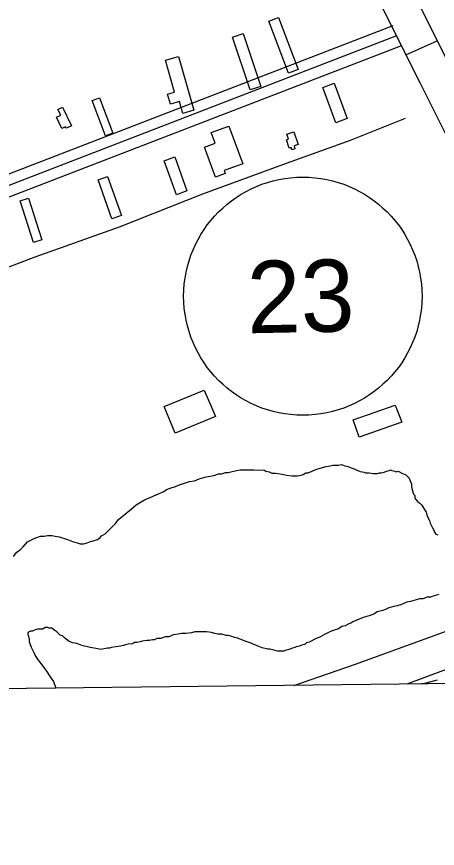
# Model space of a CAD drawing. Extents: x 3684037 to 3722149, y 433263 to 459021.
# Drawn here: x 3707277 to 3707859, y 438677 to 439830 of the extents above; entities that cross this region are included whole.
import ezdxf

# ---------------------------------------------------------------- set-up
doc = ezdxf.new("R2010")
doc.units = 0
for name, color, linetype in [('V-BLDG-OTLN', 7, 'Continuous'), ('V-GRID-FRAM', 7, 'Continuous'), ('V-LEVE-TOET', 7, 'Continuous'), ('V-RIVR-EDGE', 7, 'Continuous'), ('V-ROAD-CNTR', 7, 'Continuous'), ('V-ROAD-IDEN', 7, 'Continuous'), ('V-SITE-VEGE', 7, 'Continuous'), ('V-TOPO-SHOR', 7, 'Continuous')]:
    doc.layers.add(name, color=color, linetype=linetype)

msp = doc.modelspace()

# ---------------------------------------------------------------- linework, layer by layer
at = {"layer": 'V-BLDG-OTLN'}
for points in [[(3707638.9, 439828.7), (3707666.2, 439756.5), (3707653, 439751.5), (3707625.6, 439823.6)], [(3707590.3, 439806.6), (3707614.8, 439733.2), (3707600.1, 439728.3), (3707575.6, 439801.6)], [(3707500.6, 439774.8), (3707522, 439700.2), (3707506.8, 439695.8), (3707502.1, 439712.2), (3707489.5, 439708.6), (3707485.5, 439722.5), (3707495.3, 439725.3), (3707482.6, 439769.6)], [(3707718.7, 439682.9), (3707700.6, 439731.9), (3707716, 439737.6), (3707734.1, 439688.6)], [(3707399.6, 439664.7), (3707381.1, 439713.7), (3707391.3, 439717.6), (3707409.8, 439668.5)], [(3707340, 439704.4), (3707352.5, 439678.5), (3707345.5, 439675.2), (3707344.4, 439677.4), (3707339.2, 439674.9), (3707331.7, 439690.6), (3707337.6, 439693.4), (3707333.7, 439701.4)], [(3707589.7, 439626.2), (3707563.8, 439616.6), (3707565.2, 439612.7), (3707551.9, 439607.7), (3707536.5, 439649), (3707551.2, 439654.5), (3707545.8, 439669.2), (3707570.2, 439678.3)], [(3707650.6, 439667.1), (3707660.5, 439670.3), (3707666.2, 439652.8), (3707660.6, 439650.9), (3707661.9, 439646.8), (3707657.7, 439645.5), (3707656.7, 439648.8), (3707654, 439647.9), (3707650.3, 439659.3), (3707652.8, 439660.1)], [(3707495.5, 439635.5), (3707512.4, 439588.5), (3707497.7, 439583.2), (3707480.8, 439630.2)], [(3707408.4, 439549.8), (3707389.4, 439604), (3707402.6, 439608.6), (3707421.6, 439554.4)], [(3707293, 439578.2), (3707311.5, 439520.8), (3707300, 439517.1), (3707281.5, 439574.5)], [(3707551.9, 439275.7), (3707496, 439252.8), (3707480.9, 439289.8), (3707536.3, 439312.5)], [(3707809.9, 439267.8), (3707750.6, 439247.4), (3707742.4, 439271.3), (3707800.7, 439291.4)]]:
    msp.add_lwpolyline(points, close=True, dxfattribs=at)
at = {"layer": 'V-GRID-FRAM'}
msp.add_lwpolyline([(3688058.9, 456858.9), (3719789.3, 457228.1), (3720008.8, 439046.9), (3688262.6, 438677.5), (3688058.9, 456858.9)], dxfattribs=at)
at = {"layer": 'V-LEVE-TOET'}
for points in [[(3707660.4, 438903.2), (3707744.1, 438932.2), (3707908, 438991.9), (3707952.7, 439006.9), (3707995.6, 439019.6), (3708048.1, 439034.1), (3708079.1, 439043.2), (3708092.2, 439043.8), (3708101.2, 439040.8), (3708104.7, 439039.7), (3708107.8, 439030.7), (3708106.6, 439019.4), (3708109.7, 438988.4), (3708127.7, 438941.9), (3708140.5, 438908.8)], [(3708085.8, 438908.1), (3708078.3, 438928.6), (3708059.6, 438971.5), (3708055.4, 438980.4), (3708047.6, 438982.8), (3708006.5, 438971.9), (3707867.6, 438923.7), (3707816.9, 438905)]]:
    msp.add_lwpolyline(points, dxfattribs=at)
at = {"layer": 'V-RIVR-EDGE'}
msp.add_spline([(3705459.3, 448025.4), (3705478.2, 447991), (3705490.6, 447962.7), (3705497.9, 447946.9), (3705515.2, 447915.3), (3705550.2, 447853.8), (3705577.2, 447806.4), (3705592.1, 447777.2), (3705613, 447735.5), (3705627.1, 447702.7), (3705648.4, 447660.6), (3705670.9, 447613.3), (3705688.6, 447575.6), (3705703.1, 447542.8), (3705728.1, 447487.8), (3705750.2, 447433.1), (3705764.2, 447399.5), (3705787.6, 447350.5), (3705800.4, 447321.8), (3705823.8, 447277.7), (3705853.1, 447212.9), (3705867.2, 447179.7), (3705884.5, 447148.5), (3705906.2, 447095.5), (3705936, 447039.6), (3705952.5, 446996.3), (3705954.5, 446986.6), (3705964.5, 446959.1), (3705978.2, 446928.3), (3706001.9, 446883.8), (3706017.2, 446850.2), (3706031.3, 446824.3), (3706060.3, 446774.8), (3706084.9, 446736.8), (3706095.8, 446723.4), (3706096.2, 446720.2), (3706091.3, 446714.5), (3706089.7, 446713.3), (3706090.5, 446708.9), (3706096.1, 446705.6), (3706103, 446703.6), (3706108.6, 446696.7), (3706116.3, 446683.3), (3706130, 446657), (3706163.4, 446591.8), (3706169.4, 446575.6), (3706187.1, 446537.6), (3706212.8, 446473.6), (3706230.1, 446432.3), (3706247.4, 446398.3), (3706265.1, 446371.2), (3706278.8, 446345.3), (3706293.7, 446309.7), (3706314.6, 446262.3), (3706333.5, 446225.8), (3706356, 446180.1), (3706380.2, 446133.5), (3706396.3, 446102.4), (3706412.8, 446074.8), (3706429.7, 446038.8), (3706447, 445997.9), (3706455.4, 445962.3), (3706478.2, 445886.2), (3706492.7, 445852.2), (3706510.4, 445809.7), (3706528.1, 445771.7), (3706558.3, 445705.3), (3706582.8, 445657.1), (3706597.7, 445624.3), (3706628.3, 445558.3), (3706659.6, 445483), (3706677.7, 445432.8), (3706697, 445381), (3706750.1, 445262.4), (3706782.6, 445193.2), (3706806.8, 445141.8), (3706827.7, 445093.6), (3706851, 445029.3), (3706864.2, 444984.3), (3706871.8, 444949.5), (3706889.5, 444896.9), (3706899.9, 444865.8), (3706912.4, 444832.2), (3706928.8, 444798.2), (3706942.5, 444773.5), (3706966.3, 444725.3), (3706990.4, 444679.5), (3707017, 444624.5), (3707033.9, 444586), (3707080.5, 444482), (3707095.4, 444444.7), (3707112.3, 444405.1), (3707123.1, 444381.2), (3707171.4, 444273.5), (3707203.2, 444200.6), (3707218, 444163.8), (3707250.2, 444096.2), (3707257.4, 444074.3), (3707269.9, 444041.6), (3707288.4, 443990.6), (3707304, 443950.1), (3707343, 443838), (3707365.9, 443772), (3707378.7, 443728.7), (3707379.9, 443714.1), (3707381.1, 443702.8), (3707387.5, 443682.2), (3707398.3, 443657.1), (3707418.1, 443619), (3707439, 443578.5), (3707454.3, 443542.1), (3707473.1, 443492.7), (3707483.2, 443464.4), (3707531.1, 443368), (3707542.7, 443345), (3707550.8, 443323.9), (3707556.8, 443302.5), (3707556.8, 443297.6), (3707558.8, 443289.1), (3707568.4, 443273.3), (3707583.7, 443244.6), (3707593.8, 443221.9), (3707598.2, 443213.4), (3707609.5, 443204.9), (3707611.9, 443195.2), (3707611.9, 443180.6), (3707615.5, 443168.1), (3707621.9, 443150.3), (3707634.4, 443126.8), (3707648.1, 443102.1), (3707655.3, 443081.8), (3707660.5, 443073.3), (3707674.2, 443051.5), (3707678.6, 443034.1), (3707682.6, 443015.5), (3707689.5, 442998.5), (3707701.9, 442964.5), (3707714, 442928.4), (3707721.2, 442903.3), (3707726.4, 442888.8), (3707738.1, 442871.8), (3707743.7, 442857.2), (3707744.5, 442845.1), (3707747.3, 442826.1), (3707753.7, 442815.5), (3707763, 442801.3), (3707770.2, 442783.9), (3707772.6, 442762.1), (3707776.2, 442738.2), (3707779.8, 442720), (3707786.6, 442702.6), (3707805.5, 442663.3), (3707822.8, 442627.3), (3707832, 442599.4), (3707839.2, 442573.9), (3707845.7, 442561.3), (3707852.5, 442552.4), (3707860.2, 442541.9), (3707869.5, 442530.6), (3707886.4, 442507.9), (3707898.9, 442479.9), (3707916.1, 442434.6), (3707928.6, 442395.8), (3707943.4, 442356.5), (3707965.6, 442316.4), (3707989.7, 442269), (3708009.8, 442227.7), (3708024.7, 442192.5), (3708061.3, 442114.4), (3708074.2, 442088.5), (3708094.3, 442045.6), (3708116, 441996.6), (3708126.1, 441968.3), (3708137.7, 441927.8), (3708147.3, 441899.5), (3708157.8, 441868.3), (3708179.1, 441812.4), (3708204, 441746.9), (3708227.7, 441693.8), (3708249.8, 441646.1), (3708265.1, 441615.3), (3708271.5, 441595.9), (3708278.4, 441582.1), (3708308.1, 441508.4), (3708330.6, 441457.8), (3708349.9, 441405.2), (3708369.6, 441340.1), (3708384, 441295.6), (3708395.3, 441268.4), (3708411.8, 441234.8), (3708423.4, 441209.3), (3708441.1, 441169.7), (3708458.4, 441135.2), (3708469.3, 441110.5), (3708475.3, 441089.1), (3708486.9, 441061.6), (3708507.1, 441017.4), (3708523.5, 440978.6), (3708539.2, 440935.7), (3708564.1, 440883.1), (3708587.1, 440841.3), (3708595.1, 440826.8), (3708600.4, 440809.4), (3708606.7, 440778.2), (3708615.6, 440755.1), (3708636.9, 440692), (3708652.9, 440644.3), (3708673.4, 440592), (3708688.7, 440554.4), (3708706, 440506.6), (3708725.7, 440462.9), (3708743.4, 440422.4), (3708759.4, 440387.6), (3708800.1, 440293.3), (3708821, 440246.3), (3708835, 440211.5), (3708849.1, 440180.4), (3708876.1, 440124.9), (3708892.2, 440093.7), (3708912.3, 440054.9), (3708922.3, 440031), (3708932, 439999.8), (3708939.2, 439978.8), (3708948, 439954.1), (3708952.4, 439931.8), (3708956, 439911.6), (3708960, 439899.5), (3708969.6, 439870.3), (3708986.9, 439829.8), (3708999.4, 439794.2), (3709014.7, 439755.4), (3709034.7, 439705.2), (3709046.8, 439671.6), (3709063.3, 439633.1), (3709075.8, 439614.5), (3709093.1, 439592.6), (3709106, 439574.4), (3709121.7, 439548.9), (3709151.5, 439484.1), (3709171.6, 439447.3), (3709197.4, 439407.6), (3709211.1, 439376.8), (3709222.3, 439350.1), (3709240.4, 439308.8), (3709252.9, 439281.7), (3709266.1, 439254.9), (3709271, 439245.6), (3709296.3, 439199.9), (3709313.2, 439159), (3709331.3, 439114.9), (3709341.3, 439082.5), (3709360.3, 439046.5), (3709378.8, 439008.8), (3709407.7, 438944.4), (3709416.4, 438923.6)], degree=3, dxfattribs=at)
at = {"layer": 'V-ROAD-CNTR'}
for points in [[(3706492.4, 442521.2), (3706946.8, 441617.1), (3707489, 440536.5), (3707877, 439759.9), (3708257.7, 438990.5)], [(3706450.1, 442499.9), (3706904.6, 441595.9), (3707446.7, 440515.3), (3707834.7, 439738.8), (3708246.6, 438913.6)], [(3707797.2, 439817.1), (3706879, 439462.6)], [(3707802.6, 439803.1), (3706884.4, 439448.7)], [(3707808, 439789.1), (3706889.8, 439434.7)], [(3707815.5, 439777.1), (3707858.8, 439796.3)]]:
    msp.add_lwpolyline(points, dxfattribs=at)
at = {"layer": 'V-ROAD-IDEN'}
msp.add_circle((3707672.8, 439442.6), 165, dxfattribs=at)
at = {"layer": 'V-SITE-VEGE'}
for p, q in [((3707569.6, 439198.2), (3707581.1, 439201.2)), ((3707581.1, 439201.2), (3707585.9, 439202.1)), ((3707585.9, 439202.1), (3707605.1, 439202.2)), ((3707605.1, 439202.2), (3707610.9, 439201.3)), ((3707610.9, 439201.3), (3707618.6, 439202.2)), ((3707618.6, 439202.2), (3707621.4, 439200.3)), ((3707621.4, 439200.3), (3707626.2, 439199.4)), ((3707681.9, 439198.6), (3707684.8, 439199.6)), ((3707684.8, 439199.6), (3707688.6, 439201.5)), ((3707688.6, 439201.5), (3707693.4, 439203.4)), ((3707693.4, 439203.4), (3707704.9, 439206.4)), ((3707704.9, 439206.4), (3707710.7, 439207.3)), ((3707710.7, 439207.3), (3707714.5, 439208.3)), ((3707714.5, 439208.3), (3707722.2, 439208.3)), ((3707722.2, 439208.3), (3707726.1, 439209.3)), ((3707726.1, 439209.3), (3707730.9, 439207.4)), ((3707730.9, 439207.4), (3707735.7, 439206.5)), ((3707735.7, 439206.5), (3707739.5, 439204.6)), ((3707739.5, 439204.6), (3707742.4, 439203.6)), ((3707742.4, 439203.6), (3707752, 439199.8)), ((3707752, 439199.8), (3707757.8, 439198.9)), ((3707785.6, 439198.9), (3707788.5, 439199.9)), ((3707788.5, 439199.9), (3707792.3, 439200.9)), ((3707792.3, 439200.9), (3707794.3, 439201.9)), ((3707794.3, 439201.9), (3707796.2, 439200.9)), ((3707796.2, 439200.9), (3707800, 439200)), ((3707800, 439200), (3707801.9, 439199)), ((3707801.9, 439199), (3707804.8, 439200)), ((3707804.8, 439200), (3707810.6, 439197.1)), ((3707522.6, 439186.6), (3707529.3, 439189.5)), ((3707529.3, 439189.5), (3707538.9, 439192.4)), ((3707538.9, 439192.4), (3707544.7, 439193.4)), ((3707544.7, 439193.4), (3707549.5, 439194.3)), ((3707549.5, 439194.3), (3707556.2, 439196.3)), ((3707556.2, 439196.3), (3707560, 439196.3)), ((3707560, 439196.3), (3707565.8, 439198.2)), ((3707565.8, 439198.2), (3707569.6, 439198.2)), ((3707626.2, 439199.4), (3707630.1, 439197.5)), ((3707630.1, 439197.5), (3707634.9, 439197.5)), ((3707634.9, 439197.5), (3707641.6, 439196.6)), ((3707641.6, 439196.6), (3707646.4, 439195.6)), ((3707646.4, 439195.6), (3707650.3, 439194.7)), ((3707650.3, 439194.7), (3707657.9, 439193.7)), ((3707657.9, 439193.7), (3707665.6, 439193.8)), ((3707665.6, 439193.8), (3707670.4, 439194.7)), ((3707670.4, 439194.7), (3707673.3, 439195.7)), ((3707673.3, 439195.7), (3707677.1, 439197.6)), ((3707677.1, 439197.6), (3707680, 439197.6)), ((3707680, 439197.6), (3707681.9, 439198.6)), ((3707757.8, 439198.9), (3707759.7, 439197.9)), ((3707759.7, 439197.9), (3707764.5, 439197.9)), ((3707764.5, 439197.9), (3707770.3, 439197)), ((3707770.3, 439197), (3707776, 439197)), ((3707776, 439197), (3707778.9, 439198)), ((3707778.9, 439198), (3707781.8, 439198)), ((3707781.8, 439198), (3707785.6, 439198.9)), ((3707810.6, 439197.1), (3707813.5, 439196.2)), ((3707813.5, 439196.2), (3707815.4, 439195.2)), ((3707815.4, 439195.2), (3707820.2, 439190.4)), ((3707820.2, 439190.4), (3707821.2, 439186.6)), ((3707484.2, 439174.9), (3707489, 439176.8)), ((3707489, 439176.8), (3707496.7, 439178.8)), ((3707496.7, 439178.8), (3707500.5, 439180.7)), ((3707500.5, 439180.7), (3707506.3, 439182.7)), ((3707506.3, 439182.7), (3707515.9, 439185.6)), ((3707515.9, 439185.6), (3707522.6, 439186.6)), ((3707821.2, 439186.6), (3707823.1, 439182.7)), ((3707823.1, 439182.7), (3707823.1, 439178.9)), ((3707823.1, 439178.9), (3707824.1, 439174.1)), ((3707462.2, 439164.3), (3707469.9, 439167.2)), ((3707469.9, 439167.2), (3707480.4, 439172)), ((3707480.4, 439172), (3707484.2, 439174.9)), ((3707824.1, 439174.1), (3707826, 439168.4)), ((3707826, 439168.4), (3707828, 439166.4)), ((3707828, 439166.4), (3707828, 439162.6)), ((3707435.4, 439147.9), (3707442.1, 439153.7)), ((3707442.1, 439153.7), (3707453.6, 439160.4)), ((3707453.6, 439160.4), (3707462.2, 439164.3)), ((3707828, 439162.6), (3707829, 439160.7)), ((3707829, 439160.7), (3707831.8, 439157.8)), ((3707831.8, 439157.8), (3707834.7, 439155.9)), ((3707834.7, 439155.9), (3707837.6, 439153)), ((3707424.8, 439139.2), (3707435.4, 439147.9)), ((3707837.6, 439153), (3707841.5, 439146.3)), ((3707841.5, 439146.3), (3707843.4, 439143.5)), ((3707843.4, 439143.5), (3707844.4, 439139.6)), ((3707413.3, 439127.6), (3707418.1, 439133.4)), ((3707418.1, 439133.4), (3707424.8, 439139.2)), ((3707844.4, 439139.6), (3707846.3, 439134.8)), ((3707846.3, 439134.8), (3707848.2, 439131.9)), ((3707848.2, 439131.9), (3707849.2, 439128.1)), ((3707399, 439113.2), (3707413.3, 439127.6)), ((3707849.2, 439128.1), (3707852.1, 439121.4)), ((3707852.1, 439121.4), (3707854.1, 439118.5)), ((3707302, 439107.1), (3707309.7, 439110)), ((3707309.7, 439110), (3707314.5, 439110)), ((3707314.5, 439110), (3707319.3, 439111)), ((3707319.3, 439111), (3707326, 439111)), ((3707326, 439111), (3707329.9, 439110.1)), ((3707329.9, 439110.1), (3707335.6, 439109.1)), ((3707335.6, 439109.1), (3707347.2, 439105.3)), ((3707388.4, 439105.5), (3707392.3, 439108.4)), ((3707392.3, 439108.4), (3707394.2, 439110.3)), ((3707394.2, 439110.3), (3707399, 439113.2)), ((3707854.1, 439118.5), (3707855, 439115.6)), ((3707855, 439115.6), (3707857, 439112.8)), ((3707857, 439112.8), (3707859.8, 439111.8)), ((3707285.7, 439095.5), (3707291.5, 439102.3)), ((3707291.5, 439102.3), (3707297.2, 439105.2)), ((3707297.2, 439105.2), (3707302, 439107.1)), ((3707347.2, 439105.3), (3707349.1, 439104.4)), ((3707349.1, 439104.4), (3707353.9, 439102.5)), ((3707353.9, 439102.5), (3707360.6, 439100.6)), ((3707360.6, 439100.6), (3707364.5, 439099.6)), ((3707364.5, 439099.6), (3707369.3, 439099.6)), ((3707369.3, 439099.6), (3707374.1, 439100.6)), ((3707374.1, 439100.6), (3707378.9, 439102.6)), ((3707378.9, 439102.6), (3707382.7, 439103.5)), ((3707382.7, 439103.5), (3707388.4, 439105.5)), ((3707272.3, 439082), (3707277.1, 439087.8)), ((3707277.1, 439087.8), (3707281.9, 439091.7)), ((3707281.9, 439091.7), (3707285.7, 439095.5)), ((3707854.4, 439027.3), (3707849.6, 439025.4)), ((3707861.1, 439029.3), (3707854.4, 439027.3)), ((3707809.3, 439015.6), (3707803.5, 439013.7)), ((3707816.9, 439018.5), (3707809.3, 439015.6)), ((3707821.7, 439019.5), (3707816.9, 439018.5)), ((3707828.4, 439021.5), (3707821.7, 439019.5)), ((3707834.2, 439023.4), (3707828.4, 439021.5)), ((3707839, 439023.4), (3707834.2, 439023.4)), ((3707844.8, 439025.4), (3707839, 439023.4)), ((3707849.6, 439025.4), (3707844.8, 439025.4)), ((3707775.7, 439005), (3707770.9, 439002.1)), ((3707783.4, 439006.9), (3707775.7, 439005)), ((3707788.2, 439008.9), (3707783.4, 439006.9)), ((3707792, 439010.8), (3707788.2, 439008.9)), ((3707798.7, 439012.7), (3707792, 439010.8)), ((3707803.5, 439013.7), (3707798.7, 439012.7)), ((3707756.5, 438997.2), (3707742.1, 438991.4)), ((3707766.1, 439000.1), (3707756.5, 438997.2)), ((3707770.9, 439002.1), (3707766.1, 439000.1)), ((3707305.3, 438981.3), (3707302.4, 438980.4)), ((3707313, 438981.4), (3707305.3, 438981.3)), ((3707315.9, 438983.3), (3707313, 438981.4)), ((3707319.7, 438983.3), (3707315.9, 438983.3)), ((3707321.6, 438982.4), (3707319.7, 438983.3)), ((3707325.5, 438982.4), (3707321.6, 438982.4)), ((3707329.3, 438979.5), (3707325.5, 438982.4)), ((3707722, 438981.8), (3707713.4, 438978.8)), ((3707726.8, 438984.7), (3707722, 438981.8)), ((3707731.6, 438985.6), (3707726.8, 438984.7)), ((3707736.4, 438988.5), (3707731.6, 438985.6)), ((3707739.3, 438989.5), (3707736.4, 438988.5)), ((3707742.1, 438991.4), (3707739.3, 438989.5)), ((3707295.7, 438978.4), (3707291.9, 438976.5)), ((3707291.9, 438976.5), (3707291.9, 438973.6)), ((3707291.9, 438973.6), (3707292.9, 438971.7)), ((3707292.9, 438971.7), (3707293.9, 438966.9)), ((3707298.6, 438978.4), (3707295.7, 438978.4)), ((3707302.4, 438980.4), (3707298.6, 438978.4)), ((3707332.2, 438977.6), (3707329.3, 438979.5)), ((3707337, 438972.8), (3707332.2, 438977.6)), ((3707339.9, 438971.9), (3707337, 438972.8)), ((3707342.8, 438969), (3707339.9, 438971.9)), ((3707482, 438970.4), (3707476.3, 438968.5)), ((3707486.8, 438970.4), (3707482, 438970.4)), ((3707489.7, 438971.4), (3707486.8, 438970.4)), ((3707493.5, 438973.3), (3707489.7, 438971.4)), ((3707500.2, 438974.3), (3707493.5, 438973.3)), ((3707505, 438975.3), (3707500.2, 438974.3)), ((3707510.8, 438975.3), (3707505, 438975.3)), ((3707518.5, 438976.3), (3707510.8, 438975.3)), ((3707523.3, 438977.3), (3707518.5, 438976.3)), ((3707539.6, 438977.3), (3707523.3, 438977.3)), ((3707546.3, 438976.4), (3707539.6, 438977.3)), ((3707551.1, 438975.4), (3707546.3, 438976.4)), ((3707555, 438974.5), (3707551.1, 438975.4)), ((3707560.7, 438974.5), (3707555, 438974.5)), ((3707566.5, 438972.6), (3707560.7, 438974.5)), ((3707569.4, 438972.6), (3707566.5, 438972.6)), ((3707573.2, 438971.7), (3707569.4, 438972.6)), ((3707578, 438969.8), (3707573.2, 438971.7)), ((3707582.8, 438968.8), (3707578, 438969.8)), ((3707696.1, 438970.2), (3707691.3, 438968.2)), ((3707702.8, 438974), (3707696.1, 438970.2)), ((3707707.6, 438975.9), (3707702.8, 438974)), ((3707713.4, 438978.8), (3707707.6, 438975.9)), ((3707293.9, 438966.9), (3707293.9, 438964)), ((3707293.9, 438964), (3707294.8, 438961.2)), ((3707294.8, 438961.2), (3707296.8, 438956.4)), ((3707349.5, 438964.2), (3707342.8, 438969)), ((3707354.4, 438962.3), (3707349.5, 438964.2)), ((3707360.1, 438961.4), (3707354.4, 438962.3)), ((3707366.8, 438958.5), (3707360.1, 438961.4)), ((3707378.4, 438955.7), (3707366.8, 438958.5)), ((3707420.6, 438957.7), (3707413.9, 438956.7)), ((3707424.5, 438958.7), (3707420.6, 438957.7)), ((3707427.3, 438959.7), (3707424.5, 438958.7)), ((3707431.2, 438960.6), (3707427.3, 438959.7)), ((3707436.9, 438960.7), (3707431.2, 438960.6)), ((3707439.8, 438962.6), (3707436.9, 438960.7)), ((3707443.6, 438962.6), (3707439.8, 438962.6)), ((3707447.5, 438963.6), (3707443.6, 438962.6)), ((3707450.4, 438964.5), (3707447.5, 438963.6)), ((3707457.1, 438965.5), (3707450.4, 438964.5)), ((3707460, 438965.5), (3707457.1, 438965.5)), ((3707464.8, 438966.5), (3707460, 438965.5)), ((3707467.6, 438966.5), (3707464.8, 438966.5)), ((3707470.5, 438968.4), (3707467.6, 438966.5)), ((3707476.3, 438968.5), (3707470.5, 438968.4)), ((3707584.8, 438967.9), (3707582.8, 438968.8)), ((3707589.6, 438966), (3707584.8, 438967.9)), ((3707591.5, 438965), (3707589.6, 438966)), ((3707600.1, 438962.2), (3707591.5, 438965)), ((3707609.8, 438958.3), (3707600.1, 438962.2)), ((3707616.5, 438955.5), (3707609.8, 438958.3)), ((3707668.3, 438957.6), (3707663.5, 438956.6)), ((3707670.2, 438958.5), (3707668.3, 438957.6)), ((3707676, 438960.5), (3707670.2, 438958.5)), ((3707677.9, 438962.4), (3707676, 438960.5)), ((3707681.7, 438963.4), (3707677.9, 438962.4)), ((3707691.3, 438968.2), (3707681.7, 438963.4)), ((3707296.8, 438956.4), (3707300.6, 438948.7)), ((3707300.6, 438948.7), (3707302.6, 438943.9)), ((3707384.1, 438954.7), (3707378.4, 438955.7)), ((3707388.9, 438953.8), (3707384.1, 438954.7)), ((3707392.8, 438952.8), (3707388.9, 438953.8)), ((3707402.4, 438954.8), (3707392.8, 438952.8)), ((3707405.3, 438954.8), (3707402.4, 438954.8)), ((3707408.1, 438955.8), (3707405.3, 438954.8)), ((3707413.9, 438956.7), (3707408.1, 438955.8)), ((3707624.2, 438953.6), (3707616.5, 438955.5)), ((3707627.1, 438953.6), (3707624.2, 438953.6)), ((3707634.7, 438951.7), (3707627.1, 438953.6)), ((3707637.6, 438950.8), (3707634.7, 438951.7)), ((3707646.3, 438950.8), (3707637.6, 438950.8)), ((3707648.2, 438951.8), (3707646.3, 438950.8)), ((3707652, 438952.7), (3707648.2, 438951.8)), ((3707654.9, 438953.7), (3707652, 438952.7)), ((3707658.7, 438954.7), (3707654.9, 438953.7)), ((3707661.6, 438955.6), (3707658.7, 438954.7)), ((3707663.5, 438956.6), (3707661.6, 438955.6)), ((3707302.6, 438943.9), (3707306.4, 438938.1)), ((3707306.4, 438938.1), (3707310.3, 438933.4)), ((3707310.3, 438933.4), (3707318, 438922.8)), ((3707318, 438922.8), (3707322.8, 438915.2)), ((3707322.8, 438915.2), (3707327.6, 438908.5)), ((3707327.6, 438908.5), (3707330.7, 438899.4)), ((3707948.7, 438906.6), (3707837.3, 438905.3)), ((3707837.3, 438905.3), (3707841.7, 438906.5)), ((3707841.7, 438906.5), (3707859.4, 438910.8)), ((3707330.7, 438899.4), (3707249.1, 438898.4))]:
    msp.add_line(p, q, dxfattribs=at)
at = {"layer": 'V-TOPO-SHOR'}
msp.add_lwpolyline([(3707814.5, 439688.8), (3707738.5, 439658.2), (3707644.7, 439624.7), (3707534, 439583.8), (3707418.5, 439538.1), (3707302, 439496.8), (3707180.2, 439450.6), (3707106.1, 439422), (3706999.3, 439379.7), (3706931.4, 439352.5), (3706916, 439347.1), (3706892.6, 439339.6)], dxfattribs=at)

# ---------------------------------------------------------------- texts
at = {"layer": 'V-ROAD-IDEN'}
msp.add_text('23', height=100, rotation=1.1352, dxfattribs=at).set_placement((3707596.3, 439391.1))

doc.saveas('drawing.dxf')
